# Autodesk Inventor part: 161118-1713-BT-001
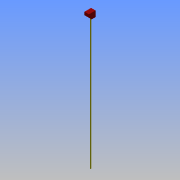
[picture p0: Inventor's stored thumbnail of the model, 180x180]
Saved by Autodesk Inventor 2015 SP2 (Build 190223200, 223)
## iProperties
Created: 2016-11
Part Number: 161118-1713-BT-001
Material: Generisch
Document SubType Name: Modeling
Designer: MP
Mass: 2191.53 g
Surface Area: 2909.76 cm^2
Volume: 2191.53 cm^3
Density: 1 g/cm^3
Appearance: Rot
Author: MP
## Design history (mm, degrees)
sketch "Skizze1"
  geometry: L1 (-50, 150)-(50, 150); L2 (50, 150)-(50, 0); L3 (50, 0)-(-50, 0); L4 (-50, 0)-(-50, 150); C1 r 30 at (0, 90); C2 r 10 at (0, 90); 2 further points
  constraints: 8 end point, 2 centre point, 2 coincident, 2 parallel, 1 horizontal, 1 midpoint, 1 perpendicular, 1 vertical alignment
  dimensions: "d0" = 100 distance of L2.end L3.end; "d1" = 150 distance of L3.end L1.start; "d2" = 60 diameter of C1; "d3" = 90 distance of point (0, 0) C1.centre; "d4" = 20 diameter of C2
extrude "Extrusion1" new body sketch "Skizze1" distance "d5" = 80; taper "d6" = 0 deg
extrude "Extrusion2" join sketch "Skizze1" distance "d7" = 10; taper "d8" = 0 deg
extrude "Extrusion3" join sketch "Skizze1" distance "d9" = 3000; taper "d10" = 0 deg
feature "Extrusionsfläche1" dims "d11" = 50, "d12" = 0
feature "Verdickung1" dims "d13" = 2, "d14" = 2
chamfer "Fase1" distance "d15" = 62.75; stored, may be unused: second distance "d16" = 2, angle "d17" = 45 deg
node "Volumenkörper1"
node "Fläche1"
